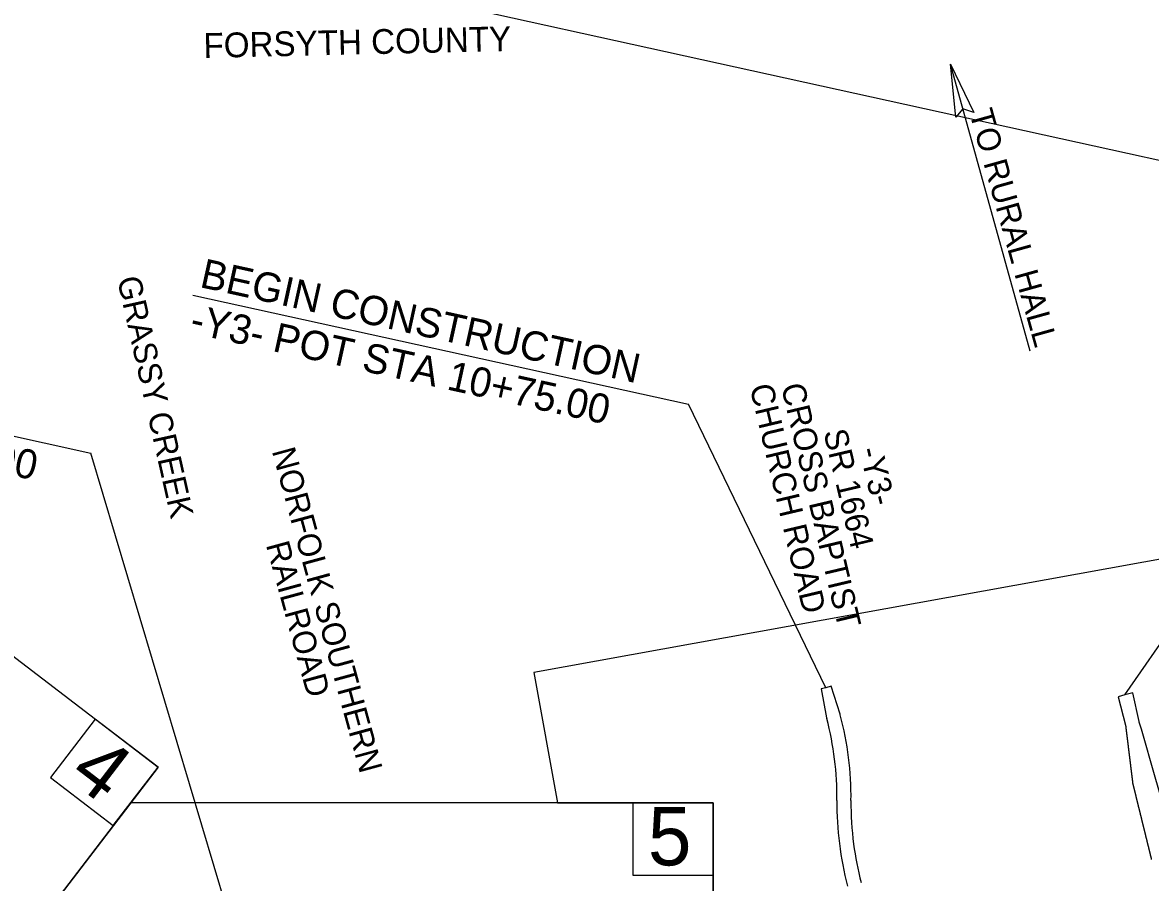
# Model space of a CAD drawing. Extents: x 1609449 to 1623942, y 894240 to 902860.
# Drawn here: x 1619483 to 1621409, y 898313 to 899782 of the extents above; entities that cross this region are included whole.
import ezdxf

# ---------------------------------------------------------------- set-up
doc = ezdxf.new("R2010")
doc.units = 0
for name, color, linetype in [('Old_Level_1', 7, 'Continuous'), ('Prop DSN Text', 7, 'Continuous'), ('Prop Horizontal Alignment Station Label', 7, 'Continuous'), ('Prop Roadway Bridge', 7, 'Continuous'), ('Prop Shade Light', 7, 'Continuous'), ('Prop Terminator CELL', 7, 'Continuous'), ('Scratch_Level_0', 7, 'Continuous'), ('Scratch_Level_1', 7, 'Continuous')]:
    doc.layers.add(name, color=color, linetype=linetype)

msp = doc.modelspace()

# ---------------------------------------------------------------- linework, layer by layer
at = {"layer": 'Old_Level_1'}
msp.add_lwpolyline([(1618675.4, 899305), (1619714, 898509.6), (1619075.6, 897675.9), (1618079.6, 898438.7)], dxfattribs=at)
for points in [[(1620396.2, 898448.3), (1620661.8, 898448.3), (1620661.8, 897662.4), (1621336.9, 897793.5), (1621466.5, 897830.2), (1621864, 897934.4), (1622007.2, 897969.4), (1621831.8, 898938.5), (1620355.8, 898671.4)], [(1619714, 898509.6), (1619606.8, 898591.7), (1619530.3, 898491.8), (1619637.6, 898409.7)], [(1619261.8, 897919), (1619261.8, 897398.3), (1620661.8, 897398.3), (1620661.8, 898448.3), (1619667.1, 898448.3)], [(1620661.8, 898448.3), (1620524.5, 898448.3), (1620524.5, 898324.8), (1620661.8, 898324.8)]]:
    msp.add_lwpolyline(points, close=True, dxfattribs=at)
at = {"layer": 'Prop DSN Text'}
msp.add_line((1621203.1, 899220.3), (1621067.2, 899710.8), dxfattribs=at)
at = {"layer": 'Prop Horizontal Alignment Station Label'}
for p, q in [((1619773.2, 899316.1), (1620619.8, 899129.6)), ((1621364.7, 898632.9), (1621724.9, 899154)), ((1620854.2, 898645.3), (1620619.8, 899129.6))]:
    msp.add_line(p, q, dxfattribs=at)
at = {"layer": 'Prop Roadway Bridge'}
for p in [(1618995.9, 899179), (1619898.8, 898041.2)]:
    msp.add_line(p, (1619599.3, 899046.1), dxfattribs=at)
at = {"layer": 'Prop Shade Light'}
for p, q in [((1620846.1, 898643.2), (1620855.4, 898593.9)), ((1620878.6, 898600.1), (1620863.6, 898647.8)), ((1621353.4, 898629.9), (1621366, 898581.5)), ((1621389.2, 898587.7), (1621378.5, 898636.6)), ((1620855.4, 898593.9), (1620855.8, 898592.5)), ((1620879, 898598.7), (1620878.6, 898600.1))]:
    msp.add_line(p, q, dxfattribs=at)
for points in [[(1620863.6, 898647.8), (1620854.2, 898645.3), (1620846.1, 898643.2)], [(1621378.5, 898636.6), (1621364.7, 898632.9), (1621353.4, 898629.9)], [(1621472.6, 898299.5), (1621468.8, 898312.4), (1621443.5, 898400), (1621426.9, 898457.3), (1621416.7, 898492.7), (1621393.1, 898574.2), (1621389.6, 898586.2), (1621389.2, 898587.7)]]:
    msp.add_lwpolyline(points, dxfattribs=at)
for centre, radius, start, end in [((1620352.3, 898458.8), 521, 359.3265, 14.8727), ((1620352.3, 898458.8), 545, 359.3265, 14.8727), ((1621418.2, 898446.2), 545, 179.3265, 194.8727), ((1621418.2, 898446.2), 521, 179.3265, 187.5072), ((1621418.2, 898446.2), 521, 187.5072, 194.8727), ((1620911.6, 898379.5), 10, 187.5066, 187.5078)]:
    msp.add_arc(centre, radius, start, end, dxfattribs=at)
for points in [[(1621366, 898581.5), (1621366, 898581.3), (1621366.1, 898581.1), (1621366.1, 898580.8), (1621366.1, 898580.6), (1621366.1, 898580.4), (1621366.2, 898580.2), (1621366.2, 898579.9), (1621366.2, 898579.7), (1621366.3, 898579.5), (1621366.3, 898579.3), (1621366.3, 898579), (1621366.3, 898578.8), (1621366.4, 898578.6), (1621366.4, 898578.4), (1621366.4, 898578.1), (1621366.4, 898577.9), (1621366.5, 898577.7), (1621366.5, 898577.5), (1621366.5, 898577.2), (1621366.6, 898577), (1621366.6, 898576.8), (1621366.6, 898576.6), (1621366.6, 898576.3), (1621366.7, 898576.1), (1621366.7, 898575.9), (1621366.7, 898575.6), (1621366.8, 898575.4), (1621366.8, 898575.2), (1621366.8, 898575), (1621366.8, 898574.7), (1621366.9, 898574.5), (1621366.9, 898574.3), (1621366.9, 898574.1), (1621366.9, 898573.8), (1621367, 898573.6), (1621367, 898573.4), (1621367, 898573.2), (1621367.1, 898572.9), (1621367.1, 898572.7), (1621367.1, 898572.5), (1621367.1, 898572.3), (1621367.2, 898572), (1621367.2, 898571.8), (1621367.2, 898571.6), (1621367.3, 898571.4), (1621367.3, 898571.1), (1621367.3, 898570.9), (1621367.3, 898570.7), (1621367.4, 898570.5), (1621367.4, 898570.2), (1621367.4, 898570), (1621367.4, 898569.8), (1621367.5, 898569.6), (1621367.5, 898569.3), (1621367.5, 898569.1), (1621367.6, 898568.9), (1621367.6, 898568.7), (1621367.6, 898568.4), (1621367.6, 898568.2), (1621367.7, 898568), (1621367.7, 898567.7), (1621367.7, 898567.5), (1621367.8, 898567.3), (1621367.8, 898567.1), (1621367.8, 898566.8), (1621367.8, 898566.6), (1621367.9, 898566.4), (1621367.9, 898566.2), (1621367.9, 898565.9), (1621367.9, 898565.7), (1621368, 898565.5), (1621368, 898565.3), (1621368, 898565.1), (1621368, 898565), (1621368.1, 898564.8)], [(1621370.1, 898548.1), (1621370.1, 898548), (1621370.1, 898547.8), (1621370.2, 898547.7), (1621370.2, 898547.4), (1621370.2, 898547.2), (1621370.3, 898547), (1621370.3, 898546.8), (1621370.3, 898546.5), (1621370.3, 898546.3), (1621370.4, 898546.1), (1621370.4, 898545.9), (1621370.4, 898545.6), (1621370.4, 898545.4), (1621370.5, 898545.2), (1621370.5, 898545), (1621370.5, 898544.7), (1621370.6, 898544.5), (1621370.6, 898544.3), (1621370.6, 898544), (1621370.6, 898543.8), (1621370.7, 898543.6), (1621370.7, 898543.4), (1621370.7, 898543.1), (1621370.8, 898542.9), (1621370.8, 898542.7), (1621370.8, 898542.5), (1621370.8, 898542.2), (1621370.9, 898542), (1621370.9, 898541.8), (1621370.9, 898541.6), (1621370.9, 898541.3), (1621371, 898541.1), (1621371, 898540.9), (1621371, 898540.7), (1621371.1, 898540.4), (1621371.1, 898540.2), (1621371.1, 898540), (1621371.1, 898539.8), (1621371.2, 898539.5), (1621371.2, 898539.3), (1621371.2, 898539.1), (1621371.3, 898538.9), (1621371.3, 898538.6), (1621371.3, 898538.4), (1621371.3, 898538.2), (1621371.4, 898538), (1621371.4, 898537.7), (1621371.4, 898537.5), (1621371.4, 898537.3), (1621371.5, 898537.1), (1621371.5, 898536.8), (1621371.5, 898536.6), (1621371.6, 898536.4), (1621371.6, 898536.1), (1621371.6, 898535.9), (1621371.6, 898535.7), (1621371.7, 898535.5), (1621371.7, 898535.2), (1621371.7, 898535), (1621371.8, 898534.8), (1621371.8, 898534.6), (1621371.8, 898534.3), (1621371.8, 898534.1), (1621371.9, 898533.9), (1621371.9, 898533.7), (1621371.9, 898533.4), (1621371.9, 898533.2), (1621372, 898533), (1621372, 898532.8), (1621372, 898532.5), (1621372.1, 898532.3), (1621372.1, 898532.1), (1621372.1, 898531.9), (1621372.1, 898531.6), (1621372.2, 898531.4)], [(1621376.3, 898498), (1621376.3, 898497.9), (1621376.3, 898497.7), (1621376.3, 898497.6), (1621376.4, 898497.3), (1621376.4, 898497.1), (1621376.4, 898496.9), (1621376.4, 898496.6), (1621376.5, 898496.4), (1621376.5, 898496.2), (1621376.5, 898496), (1621376.6, 898495.7), (1621376.6, 898495.5), (1621376.6, 898495.3), (1621376.6, 898495.1), (1621376.7, 898494.8), (1621376.7, 898494.6), (1621376.7, 898494.4), (1621376.8, 898494.2), (1621376.8, 898493.9), (1621376.8, 898493.7), (1621376.8, 898493.5), (1621376.9, 898493.3), (1621376.9, 898493), (1621376.9, 898492.8), (1621376.9, 898492.6), (1621377, 898492.4), (1621377, 898492.1), (1621377, 898491.9), (1621377.1, 898491.7), (1621377.1, 898491.5), (1621377.1, 898491.2), (1621377.1, 898491), (1621377.2, 898490.8), (1621377.2, 898490.6), (1621377.2, 898490.3), (1621377.3, 898490.1), (1621377.3, 898489.9), (1621377.3, 898489.6), (1621377.3, 898489.4), (1621377.4, 898489.2), (1621377.4, 898489), (1621377.4, 898488.7), (1621377.4, 898488.5), (1621377.5, 898488.3), (1621377.5, 898488.1), (1621377.5, 898487.8), (1621377.6, 898487.6), (1621377.6, 898487.4), (1621377.6, 898487.2), (1621377.6, 898486.9), (1621377.7, 898486.7), (1621377.7, 898486.5), (1621377.7, 898486.3), (1621377.8, 898486), (1621377.8, 898485.8), (1621377.8, 898485.6), (1621377.8, 898485.4), (1621377.9, 898485.1), (1621377.9, 898484.9), (1621377.9, 898484.7), (1621377.9, 898484.5), (1621378, 898484.2), (1621378, 898484), (1621378, 898483.8), (1621378.1, 898483.6), (1621378.1, 898483.3), (1621378.1, 898483.1), (1621378.1, 898482.9), (1621378.2, 898482.7), (1621378.2, 898482.2), (1621378.3, 898481.7), (1621378.3, 898481.3)], [(1621378.3, 898481.3), (1621378.4, 898481), (1621378.5, 898480.7), (1621378.5, 898480.4), (1621378.6, 898480.1), (1621378.7, 898479.8), (1621378.8, 898479.5), (1621378.8, 898479.3), (1621378.9, 898479), (1621379, 898478.7), (1621379.1, 898478.4), (1621379.1, 898478.1), (1621379.2, 898477.8), (1621379.3, 898477.5), (1621379.3, 898477.2), (1621379.4, 898476.9), (1621379.5, 898476.6), (1621379.6, 898476.3), (1621379.6, 898476), (1621379.7, 898475.8), (1621379.8, 898475.5), (1621379.8, 898475.2), (1621379.9, 898474.9), (1621380, 898474.6), (1621380.1, 898474.3), (1621380.1, 898474), (1621380.2, 898473.7), (1621380.3, 898473.4), (1621380.3, 898473.1), (1621380.4, 898472.8), (1621380.5, 898472.5), (1621380.6, 898472.3), (1621380.6, 898472), (1621380.7, 898471.7), (1621380.8, 898471.4), (1621380.8, 898471.1), (1621380.9, 898470.8), (1621381, 898470.5), (1621381.1, 898470.2), (1621381.1, 898469.9), (1621381.2, 898469.6), (1621381.3, 898469.3), (1621381.4, 898469.1), (1621381.4, 898468.8), (1621381.5, 898468.5), (1621381.6, 898468.2), (1621381.6, 898467.9), (1621381.7, 898467.6), (1621381.8, 898467.3), (1621381.9, 898467), (1621381.9, 898466.7), (1621382, 898466.4), (1621382.1, 898466.1), (1621382.1, 898465.8), (1621382.2, 898465.6), (1621382.3, 898465.3), (1621382.4, 898465), (1621382.4, 898464.7), (1621382.5, 898464.4), (1621382.6, 898464.1), (1621382.6, 898463.8), (1621382.7, 898463.5), (1621382.8, 898463.2), (1621382.9, 898462.9), (1621382.9, 898462.6), (1621383, 898462.3), (1621383.1, 898462.1), (1621383.1, 898461.8), (1621383.2, 898461.5), (1621383.3, 898461.2), (1621383.4, 898460.9), (1621383.4, 898460.6), (1621383.5, 898460.3), (1621383.6, 898460.1), (1621383.6, 898459.9), (1621383.6, 898459.7)], [(1621389, 898438.1), (1621389, 898437.9), (1621389.1, 898437.7), (1621389.1, 898437.6), (1621389.2, 898437.3), (1621389.3, 898437), (1621389.3, 898436.7), (1621389.4, 898436.4), (1621389.5, 898436.1), (1621389.5, 898435.8), (1621389.6, 898435.5), (1621389.7, 898435.2), (1621389.8, 898434.9), (1621389.8, 898434.6), (1621389.9, 898434.3), (1621390, 898434.1), (1621390, 898433.8), (1621390.1, 898433.5), (1621390.2, 898433.2), (1621390.3, 898432.9), (1621390.3, 898432.6), (1621390.4, 898432.3), (1621390.5, 898432), (1621390.5, 898431.7), (1621390.6, 898431.4), (1621390.7, 898431.1), (1621390.8, 898430.8), (1621390.8, 898430.6), (1621390.9, 898430.3), (1621391, 898430), (1621391, 898429.7), (1621391.1, 898429.4), (1621391.2, 898429.1), (1621391.3, 898428.8), (1621391.3, 898428.5), (1621391.4, 898428.2), (1621391.5, 898427.9), (1621391.6, 898427.6), (1621391.6, 898427.3), (1621391.7, 898427.1), (1621391.8, 898426.8), (1621391.8, 898426.5), (1621391.9, 898426.2), (1621392, 898425.9), (1621392.1, 898425.6), (1621392.1, 898425.3), (1621392.2, 898425), (1621392.3, 898424.7), (1621392.3, 898424.4), (1621392.4, 898424.1), (1621392.5, 898423.8), (1621392.6, 898423.6), (1621392.6, 898423.3), (1621392.7, 898423), (1621392.8, 898422.7), (1621392.8, 898422.4), (1621392.9, 898422.1), (1621393, 898421.8), (1621393.1, 898421.5), (1621393.1, 898421.2), (1621393.2, 898420.9), (1621393.3, 898420.6), (1621393.3, 898420.3), (1621393.4, 898420.1), (1621393.5, 898419.8), (1621393.6, 898419.5), (1621393.6, 898419.2), (1621393.7, 898418.9), (1621393.8, 898418.6), (1621393.9, 898418.3), (1621393.9, 898418), (1621394, 898417.7), (1621394.1, 898417.4), (1621394.1, 898417.1), (1621394.2, 898416.8), (1621394.3, 898416.6)], [(1621394.3, 898416.6), (1621394.4, 898416.3), (1621394.4, 898416), (1621394.5, 898415.7), (1621394.6, 898415.4), (1621394.6, 898415.1), (1621394.7, 898414.8), (1621394.8, 898414.5), (1621394.9, 898414.2), (1621394.9, 898413.9), (1621395, 898413.6), (1621395.1, 898413.3), (1621395.1, 898413.1), (1621395.2, 898412.8), (1621395.3, 898412.5), (1621395.4, 898412.2), (1621395.4, 898411.9), (1621395.5, 898411.6), (1621395.6, 898411.3), (1621395.6, 898411), (1621395.7, 898410.7), (1621395.8, 898410.4), (1621395.9, 898410.1), (1621395.9, 898409.8), (1621396, 898409.6), (1621396.1, 898409.3), (1621396.2, 898409), (1621396.2, 898408.7), (1621396.3, 898408.4), (1621396.4, 898408.1), (1621396.4, 898407.8), (1621396.5, 898407.5), (1621396.6, 898407.2), (1621396.7, 898406.9), (1621396.7, 898406.6), (1621396.8, 898406.4), (1621396.9, 898406.1), (1621396.9, 898405.8), (1621397, 898405.5), (1621397.1, 898405.2), (1621397.2, 898404.9), (1621397.2, 898404.6), (1621397.3, 898404.3), (1621397.4, 898404), (1621397.4, 898403.7), (1621397.5, 898403.4), (1621397.6, 898403.1), (1621397.7, 898402.9), (1621397.7, 898402.6), (1621397.8, 898402.3), (1621397.9, 898402), (1621397.9, 898401.7), (1621398, 898401.4), (1621398.1, 898401.1), (1621398.2, 898400.8), (1621398.2, 898400.5), (1621398.3, 898400.2), (1621398.4, 898399.9), (1621398.4, 898399.6), (1621398.5, 898399.4), (1621398.6, 898399.1), (1621398.7, 898398.8), (1621398.7, 898398.5), (1621398.8, 898398.2), (1621398.9, 898397.9), (1621399, 898397.6), (1621399, 898397.3), (1621399.1, 898397), (1621399.2, 898396.7), (1621399.2, 898396.4), (1621399.3, 898396.1), (1621399.4, 898395.9), (1621399.5, 898395.6), (1621399.5, 898395.4), (1621399.6, 898395.2), (1621399.6, 898395)]]:
    msp.add_open_spline(points, degree=3, dxfattribs=at)
for points in [[(1621368.1, 898564.8), (1621368.1, 898564.6), (1621368.2, 898563.9), (1621368.3, 898563.2), (1621368.3, 898562.6), (1621368.4, 898561.9), (1621368.5, 898561.2), (1621368.6, 898560.5), (1621368.7, 898559.8), (1621368.8, 898559.2), (1621368.8, 898558.5), (1621368.9, 898557.8), (1621369, 898557.1), (1621369.1, 898556.5), (1621369.2, 898555.8), (1621369.3, 898555.1), (1621369.3, 898554.4), (1621369.4, 898553.8), (1621369.5, 898553.1), (1621369.6, 898552.4), (1621369.7, 898551.7), (1621369.8, 898551), (1621369.8, 898550.4), (1621369.9, 898549.7), (1621370, 898549), (1621370.1, 898548.3), (1621370.1, 898548.1)], [(1621372.2, 898531.4), (1621372.3, 898530.7), (1621372.3, 898530.1), (1621372.4, 898529.4), (1621372.5, 898528.7), (1621372.6, 898528), (1621372.7, 898527.3), (1621372.8, 898526.7), (1621372.8, 898526), (1621372.9, 898525.3), (1621373, 898524.6), (1621373.1, 898524), (1621373.2, 898523.3), (1621373.3, 898522.6), (1621373.3, 898521.9), (1621373.4, 898521.3), (1621373.5, 898520.6), (1621373.6, 898519.9), (1621373.7, 898519.2), (1621373.8, 898518.5), (1621373.8, 898517.9), (1621373.9, 898517.2), (1621374, 898516.5), (1621374.1, 898515.8), (1621374.2, 898515.2), (1621374.2, 898514.7)], [(1621374.2, 898514.7), (1621374.3, 898514.5), (1621374.3, 898513.8), (1621374.4, 898513.1), (1621374.5, 898512.4), (1621374.6, 898511.8), (1621374.7, 898511.1), (1621374.8, 898510.4), (1621374.8, 898509.7), (1621374.9, 898509.1), (1621375, 898508.4), (1621375.1, 898507.7), (1621375.2, 898507), (1621375.3, 898506.4), (1621375.3, 898505.7), (1621375.4, 898505), (1621375.5, 898504.3), (1621375.6, 898503.6), (1621375.7, 898503), (1621375.8, 898502.3), (1621375.8, 898501.6), (1621375.9, 898500.9), (1621376, 898500.3), (1621376.1, 898499.6), (1621376.2, 898498.9), (1621376.3, 898498.2), (1621376.3, 898498)], [(1621383.6, 898459.7), (1621383.7, 898459.4), (1621383.9, 898458.6), (1621384.2, 898457.7), (1621384.4, 898456.8), (1621384.6, 898455.9), (1621384.8, 898455.1), (1621385, 898454.2), (1621385.2, 898453.3), (1621385.4, 898452.4), (1621385.7, 898451.6), (1621385.9, 898450.7), (1621386.1, 898449.8), (1621386.3, 898448.9), (1621386.5, 898448.1), (1621386.7, 898447.2), (1621387, 898446.3), (1621387.2, 898445.4), (1621387.4, 898444.6), (1621387.6, 898443.7), (1621387.8, 898442.8), (1621388, 898441.9), (1621388.2, 898441.1), (1621388.5, 898440.2), (1621388.7, 898439.3), (1621388.9, 898438.4), (1621389, 898438.1)], [(1621399.6, 898395), (1621399.7, 898394.7), (1621399.9, 898393.8), (1621400.1, 898392.9), (1621400.3, 898392.1), (1621400.5, 898391.2), (1621400.7, 898390.3), (1621401, 898389.4), (1621401.2, 898388.6), (1621401.4, 898387.7), (1621401.6, 898386.8), (1621401.8, 898385.9), (1621402, 898385.1), (1621402.3, 898384.2), (1621402.5, 898383.3), (1621402.7, 898382.4), (1621402.9, 898381.6), (1621403.1, 898380.7), (1621403.3, 898379.8), (1621403.5, 898378.9), (1621403.8, 898378.1), (1621404, 898377.2), (1621404.2, 898376.3), (1621404.4, 898375.4), (1621404.6, 898374.6), (1621404.8, 898373.7), (1621404.9, 898373.4)], [(1621404.9, 898373.4), (1621405.1, 898372.8), (1621405.3, 898371.9), (1621405.5, 898371.1), (1621405.7, 898370.2), (1621405.9, 898369.3), (1621406.1, 898368.4), (1621406.4, 898367.6), (1621406.6, 898366.7), (1621406.8, 898365.8), (1621407, 898364.9), (1621407.2, 898364.1), (1621407.4, 898363.2), (1621407.6, 898362.3), (1621407.9, 898361.4), (1621408.1, 898360.6), (1621408.3, 898359.7), (1621408.5, 898358.8), (1621408.7, 898357.9), (1621408.9, 898357.1), (1621409.2, 898356.2), (1621409.4, 898355.3), (1621409.6, 898354.4), (1621409.8, 898353.6), (1621410, 898352.7), (1621410.2, 898351.8)]]:
    msp.add_spline(points, degree=3, dxfattribs=at)
at = {"layer": 'Prop Terminator CELL'}
msp.add_lwpolyline([(1621076.3, 899620), (1621067.2, 899710.8), (1621106.8, 899627.9), (1621088.3, 899634.7)], close=True, dxfattribs=at)
at = {"layer": 'Scratch_Level_0'}
msp.add_lwpolyline([(1615937.3, 900755.3), (1622890.3, 899223.5), (1622107.1, 895668.6), (1615154.1, 897200.4)], close=True, dxfattribs=at)
at = {"layer": 'Scratch_Level_1'}
msp.add_lwpolyline([(1615937.3, 900755.3), (1622890.3, 899223.5), (1622107.1, 895668.6), (1615154.1, 897200.4)], close=True, dxfattribs=at)

# ---------------------------------------------------------------- texts
at = {"layer": 'Old_Level_1'}
for s, rotation, p in [('4', 322.554, (1619558.1, 898490.3)), ('5', 360, (1620550.5, 898341.7))]:
    msp.add_text(s, height=100, rotation=rotation, dxfattribs=at).set_placement(p)
at = {"layer": 'Prop Horizontal Alignment Station Label'}
for s, height, rotation, p in [('FORSYTH COUNTY', 42.35, 1.3164, (1619792.1, 899721.3)), ('TO RURAL HALL', 40, 285.6231, (1621099.1, 899628)), ('BEGIN CONSTRUCTION', 50, 347.5755, (1619783.5, 899330.1)), ('GRASSY CREEK', 40, 282.6227, (1619644, 899343.8)), ('-Y3- POT STA 10+75.00', 50, 347.5755, (1619766.3, 899252)), ('CHURCH ROAD', 40, 283.3127, (1620724, 899159.6)), ('CROSS BAPTIST ', 40, 283.3127, (1620777.6, 899160.7)), ('SR 1664', 40, 283.3127, (1620850.1, 899082.3)), ('NORFOLK SOUTHERN', 40, 285.2967, (1619908.1, 899049.9)), ('-Y3-', 40, 283.3127, (1620911.1, 899052)), ('RAILROAD', 40, 285.2967, (1619898, 898889.6))]:
    msp.add_text(s, height=height, rotation=rotation, dxfattribs=at).set_placement(p)
at = {"layer": 'Prop Roadway Bridge'}
msp.add_text('-L- STA 31+71.00', height=50, rotation=347.5755, dxfattribs=at).set_placement((1618984.7, 899113.5))

doc.saveas('drawing.dxf')
